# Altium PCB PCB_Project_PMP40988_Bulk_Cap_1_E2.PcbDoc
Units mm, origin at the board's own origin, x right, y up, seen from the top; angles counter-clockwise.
Board outline 29.99 x 33.8 mm, 2 copper layers (Top Layer, Bottom Layer), stack 1.646 mm thick; 1 components, 2 nets, 2 pads, 50 vias.
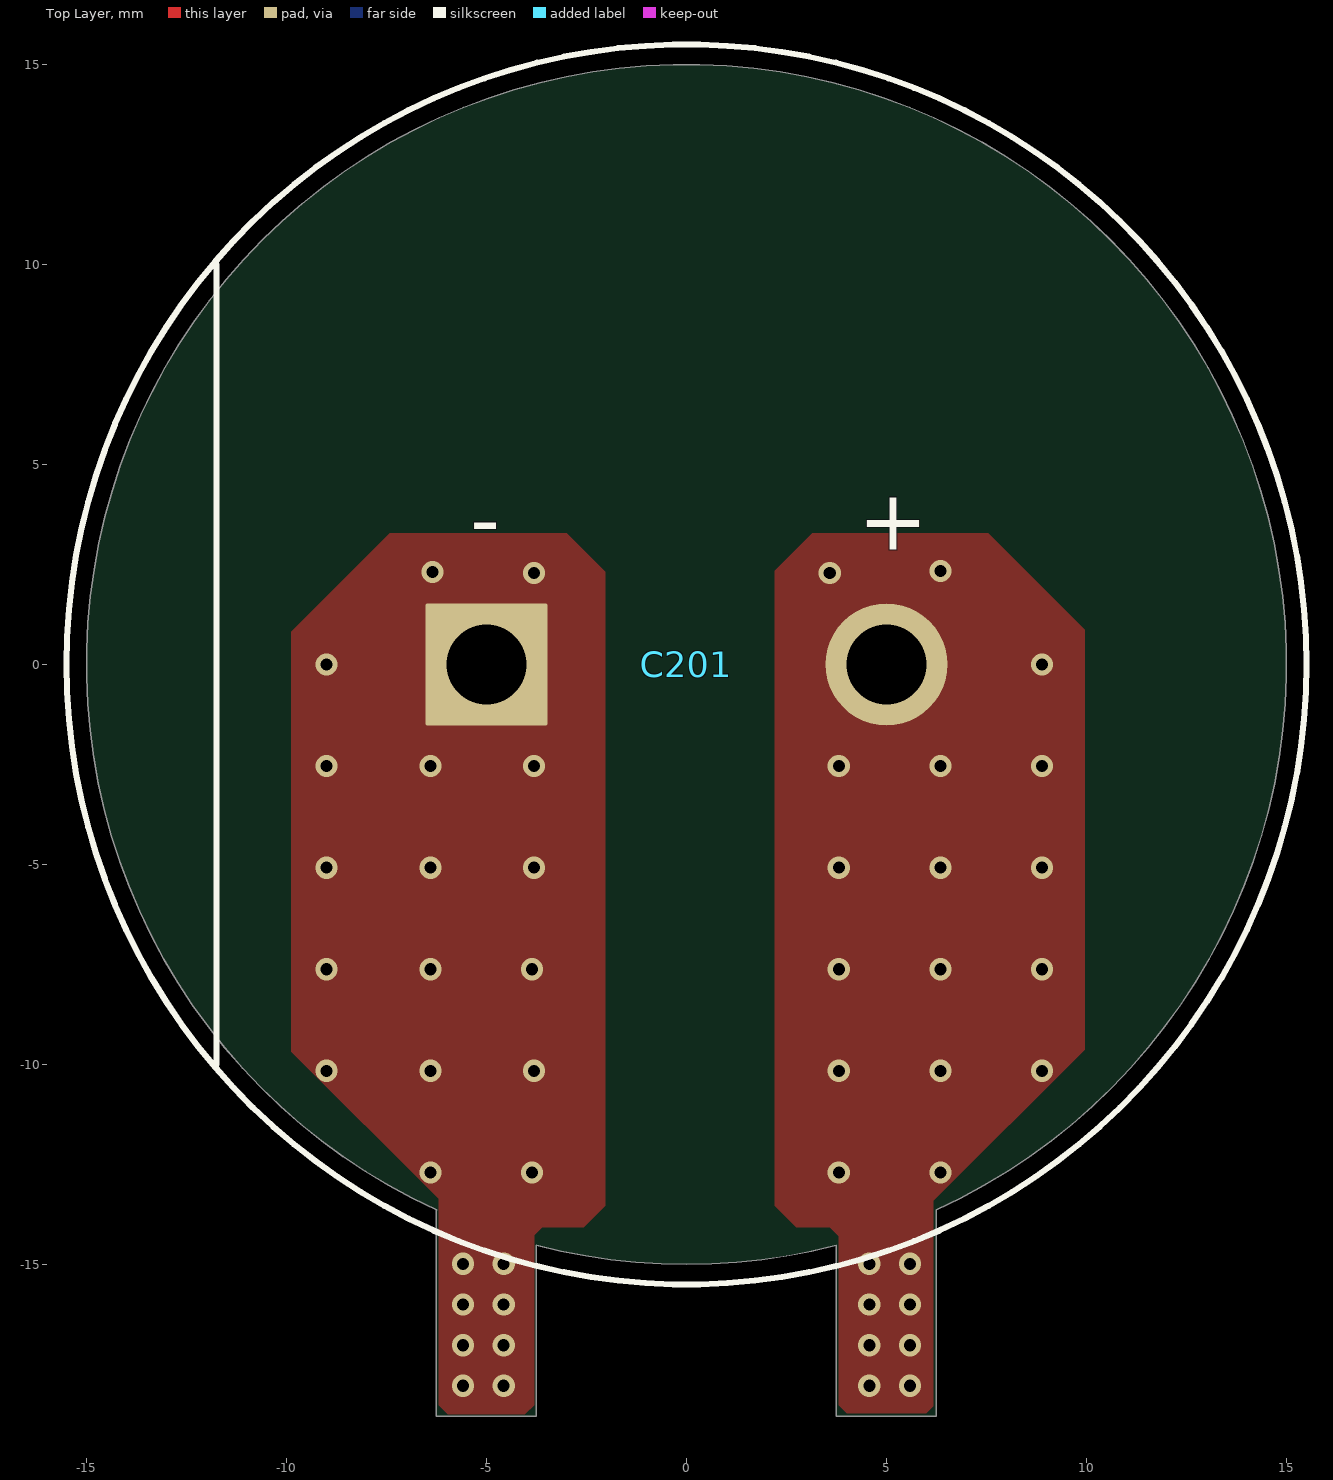
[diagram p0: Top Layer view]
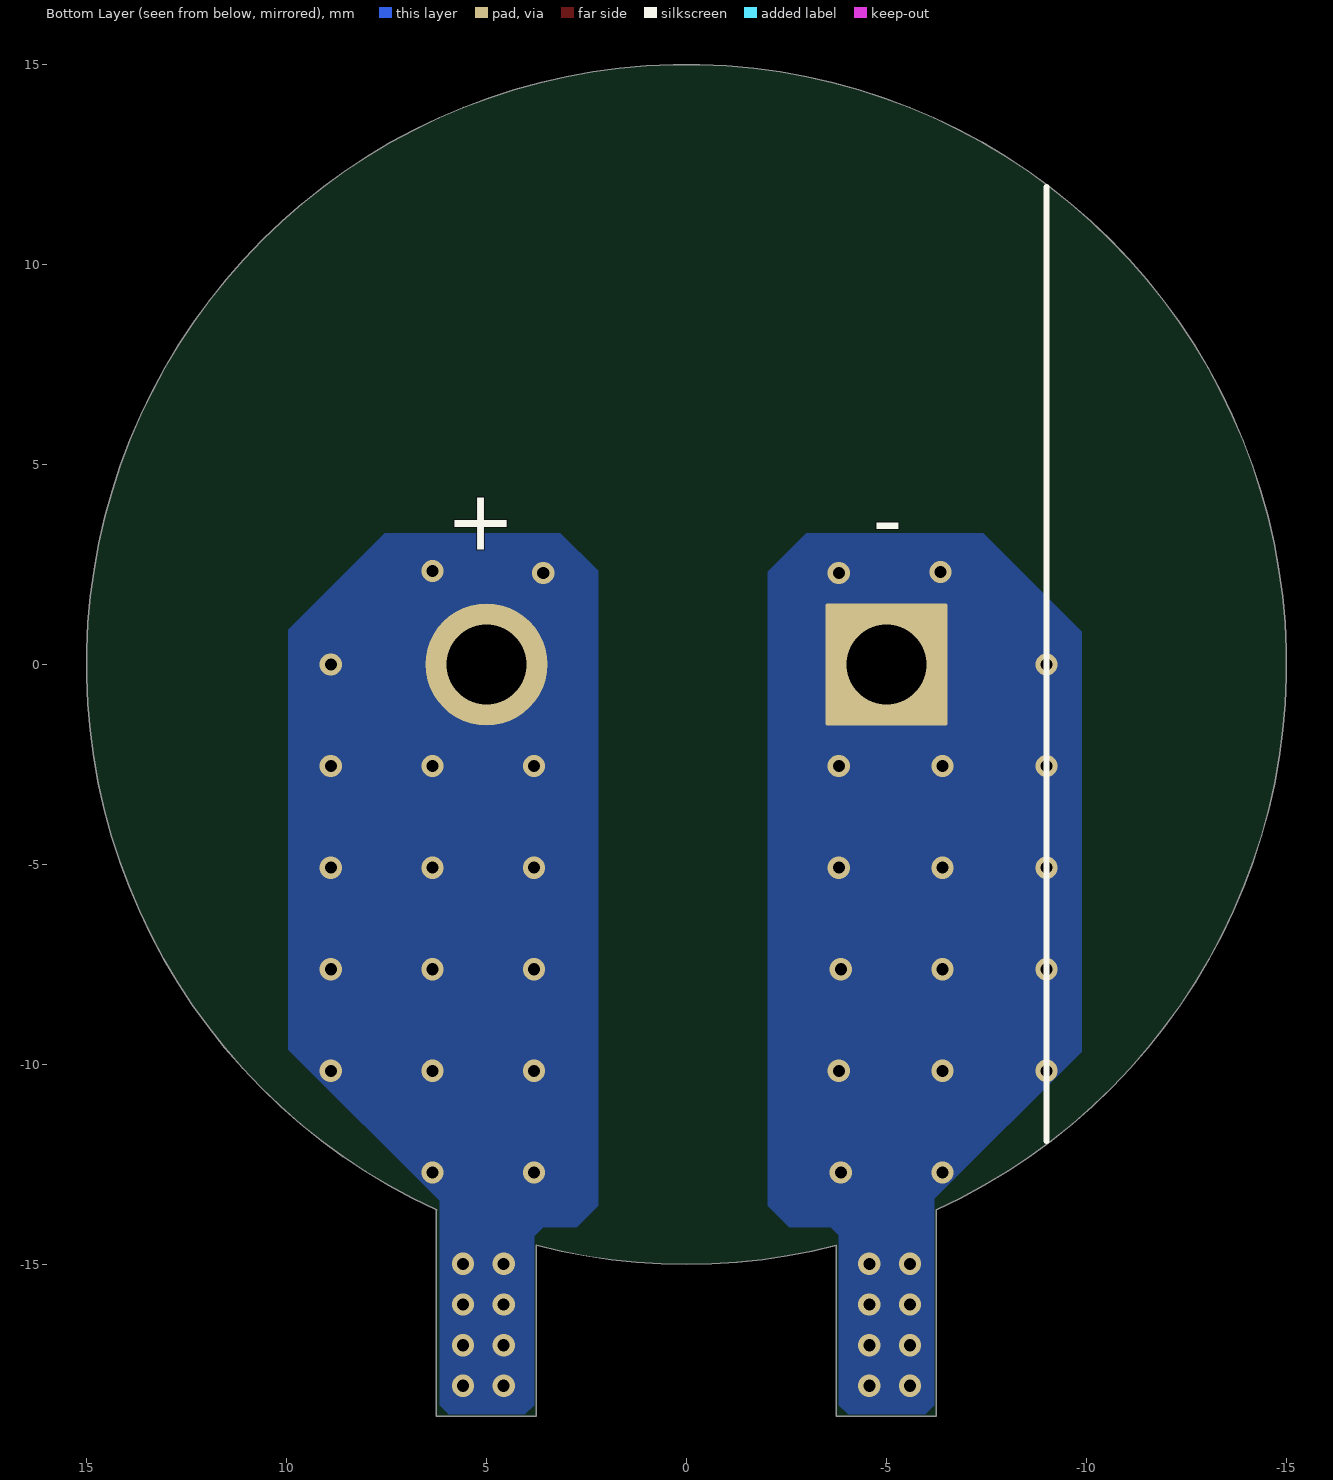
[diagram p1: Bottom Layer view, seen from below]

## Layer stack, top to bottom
Top Solder: solder mask 0.0102, Solder Resist, Dk 3.5
Top Layer: signal copper 0.0711
Dielectric1: core 1.5037, FR-4 High Tg, Dk 4.8
Bottom Layer: signal copper 0.0711
Bottom Solder: solder mask 0.0102, Solder Resist, Dk 3.5

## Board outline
-6.25,-18.8 -3.75,-18.8 -3.75,-14.526 -3.75,-14.524 ccw(c0,0) 3.743,-14.526 3.75,-14.526 3.75,-18.8 6.25,-18.8 6.25,-13.642 6.248,-13.637 ccw(c0,0) -6.248,-13.637 -6.25,-13.642

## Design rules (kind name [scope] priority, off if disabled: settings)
AcuteAngle [All] p1: minimum=4.50000000000000E+0001 checktracksonly=FALSE
AssemblyTestPointUsage [All] p1: valid=2
Clearance Clearance_3 [InNet('EARTH') vs Not InNet('EARTH') And Not InNet('12VS')] p1: gap=5.08 ignorepadtopadclearanceinfootprint=FALSE except(0: Arc-Hole Track-Hole SMDPad-Hole THPad-Hole Via-Hole Fill-Hole Poly-Hole Region-Hole Text-Hole)
Clearance Clearance_1 [InNetClass('HV') vs InNetClass('MV')] p2: gap=0.635 ignorepadtopadclearanceinfootprint=FALSE except(0: Arc-Hole Track-Hole SMDPad-Hole THPad-Hole Via-Hole Fill-Hole Poly-Hole Region-Hole Text-Hole)
Clearance Clearance_2 [InNetClass('HV') vs Not InNetClass('HV')] p3: gap=1.27 ignorepadtopadclearanceinfootprint=FALSE except(0: Arc-Hole Track-Hole SMDPad-Hole THPad-Hole Via-Hole Fill-Hole Poly-Hole Region-Hole Text-Hole)
Clearance Clearance_Keepouts [((IsTrack Or IsArc) And Not InPoly) And IsFree and IsKeepOut vs ((IsTrack Or IsArc) And Not InPoly) And IsFree and IsKeepOut] p4: gap=0 ignorepadtopadclearanceinfootprint=FALSE
Clearance Clearance_BoardEdge_MountingHoles [OnCopper and InComponentClass('Mounting Holes') vs IsKeepOut] p5: gap=1.016 ignorepadtopadclearanceinfootprint=FALSE except(0: Arc-Hole Track-Hole SMDPad-Hole THPad-Hole Via-Hole Fill-Hole Poly-Hole Region-Hole Text-Hole)
Clearance Clearance_BoardEdge_Poly [OnCopper and InPoly vs IsKeepOut] p6: gap=0.635 ignorepadtopadclearanceinfootprint=FALSE except(0: Arc-Hole Track-Hole SMDPad-Hole THPad-Hole Via-Hole Fill-Hole Poly-Hole Region-Hole Text-Hole)
Clearance Clearance_BoardEdge [OnCopper and Not InComponentClass('Logo') and not InComponentClass('FiducialMark') and not InRegion(1000,500,4000,800) and Not IsKeepout vs IsKeepOut] p7: gap=1.905 ignorepadtopadclearanceinfootprint=FALSE except(0: Arc-Hole Track-Hole SMDPad-Hole THPad-Hole Via-Hole Fill-Hole Poly-Hole Region-Hole Text-Hole)
Clearance Clearance_Poly [InPolygon] p8: gap=0.254 ignorepadtopadclearanceinfootprint=FALSE except(0: Arc-Hole Track-Hole SMDPad-Hole THPad-Hole Via-Hole Fill-Hole Poly-Hole Region-Hole Text-Hole)
Clearance [All] p9: gap=0.2 ignorepadtopadclearanceinfootprint=FALSE except(0: Arc-Hole Track-Hole SMDPad-Hole THPad-Hole Via-Hole Fill-Hole Poly-Hole Region-Hole Text-Hole)
ComponentClearance ComponentClearance_MountingHoles_FiducialMarks [InComponentClass('Mounting Holes') vs InComponentClass('FiducialMark')] p1: gap=0.508 collisioncheckmode=3 verticalgap=0.254 showdistances=FALSE
ComponentClearance ComponentClearance_Shunt [InComponentClass('Header') vs InComponentClass('Shunt')] p2: gap=0 collisioncheckmode=3 verticalgap=0 showdistances=FALSE
ComponentClearance ComponentClearance_Logo [InComponentClass('Logo')] p3: gap=0.127 collisioncheckmode=3 verticalgap=0.254 showdistances=FALSE
ComponentClearance ComponentClearance_ScrewToNut [(HasFootprint('NY PMS 440 0025 PH')) vs (HasFootprint('Keystone_1902C'))] p4: gap=0.508 collisioncheckmode=3 verticalgap=2540 showdistances=FALSE
ComponentClearance ComponentClearance_MountingHoles [InComponentClass('Mounting Holes')] p5: gap=0.508 collisioncheckmode=3 verticalgap=0.254 showdistances=FALSE
ComponentClearance ComponentClearance_SmallPassives [HasFootprint('0201*') or HasFootprint('0402*') or HasFootprint('0508') or HasFootprint('0603*') or HasFootprint('0612') or HasFootprint('0805*') or HasFootprint('0815*') or HasFootprint('0830*') or HasFootprint('1206*') or HasFootprint('1210*') or HasFootprint('1808*') or HasFootprint('1812*') or HasFootprint('1825*') or HasFootprint('2010*') or HasFootprint('2220*') or HasFootprint('2225*') or HasFootprint('2512*') or HasFootprint('2728*') or HasFootprint('3518*') vs HasFootprint('0201*') or HasFootprint('0402*') or HasFootprint('0508') or HasFootprint('0603*') or HasFootprint('0612') or HasFootprint('0805*') or HasFootprint('0815*') or HasFootprint('0830*') or HasFootprint('1206*') or HasFootprint('1210*') or HasFootprint('1808*') or HasFootprint('1812*') or HasFootprint('1825*') or HasFootprint('2010*') or HasFootprint('2220*') or HasFootprint('2225*') or HasFootprint('2512*') or HasFootprint('2728*') or HasFootprint('3518*')] p6: gap=0.508 collisioncheckmode=3 verticalgap=0.508 showdistances=FALSE
ComponentClearance ComponentClearance_THtoSMT [IsThruComponent vs IsSMTComponent] p7: gap=0.254 collisioncheckmode=3 verticalgap=0.254 showdistances=FALSE
ComponentClearance ComponentClearance_THtoTH [IsThruComponent vs IsThruComponent] p8: gap=0.254 collisioncheckmode=3 verticalgap=0.254 showdistances=FALSE
ComponentClearance [All] p9: gap=0.254 collisioncheckmode=3 verticalgap=0.254 showdistances=FALSE
DiffPairsRouting [All] p1: maxlimit=2.54 minlimit=0.254 mostfreqgap=0.254 toplayer_minwidth=0.381 toplayer_maxwidth=0.381 toplayer_prefwidth=0.381 bottomlayer_minwidth=0.381 bottomlayer_maxwidth=0.381 bottomlayer_prefwidth=0.381 maxuncoupledlength=25.4
FabricationTestPointUsage TestPointUsage [All] p1: valid=2 allowmultiple=FALSE
FabricationTestpoint Testpoint [All] p1: side=3 testpointundercomponent=TRUE minsize=1.016 maxsize=2.54 preferedsize=1.524 minholesize=0 maxholesize=1.016 preferedholesize=0.813 testpointgrid=0.025 allowsidetop=TRUE allowsidebottom=TRUE usegrid=TRUE gridtolerance=0
FanoutControl Fanout_LCC [IsLCC] p1: bgadir=Out bgaviamode=Centered fanoutstyle=Auto fanoutdirection=Alternating viagrid=0.025 // Fanout_LCC (Default Rule)
FanoutControl Fanout_BGA [IsBGA] p2: bgadir=Out bgaviamode=Centered fanoutstyle=Auto fanoutdirection=Alternating viagrid=0.025 // Fanout_BGA (Default Rule)
FanoutControl Fanout_Default [All] p4: bgadir=Out bgaviamode=Centered fanoutstyle=Auto fanoutdirection=Alternating viagrid=0.025 // Fanout_Default (Default Rule)
FanoutControl Fanout_Small [(CompPinCount < 5)] p5: bgadir=Out bgaviamode=Centered fanoutstyle=Auto fanoutdirection=OutThenIn viagrid=0.025 // Fanout_Small (Default Rule)
Height [All] p1: minheight=0 maxheight=76.2 prefheight=12.7
HoleSize [All] p1: absolutevalues=TRUE maxlimit=6.375 minlimit=0.178 maxpercent=80.000 minpercent=20.000
MinimumAnnularRing MinimumAnnularRing_ThermalPadVias [IsVia and InAnyComponent] p1: minimumring=0.15
MinimumAnnularRing [All] p2: minimumring=0.124
MinimumSolderMaskSliver MinimumSolderMaskSliver_Logo [InComponentClass('Logo') vs InComponentClass('Logo')] p1: minsoldermaskwidth=0.018
MinimumSolderMaskSliver [All] p2: minsoldermaskwidth=0.051
PlaneConnect [All] p1: planeconnectstyle=Direct reliefexpansion=0.254 reliefentries=4 reliefconductorwidth=0.254 reliefairgap=0.254
PolygonConnect [All] p1: connectstyle=Direct reliefconductorwidth=0.254 reliefentries=4 polygonreliefangle="90 Angle" airgapwidth=0.254
RoutingVias ThermalPadVias [IsVia and InAnyComponent] p1: holewidth=0.2 width=0.5 viastyle="Through Hole" minholewidth=0.2 minwidth=0.5 maxholewidth=0.33 maxwidth=0.6
RoutingVias [All] p2: holewidth=0.406 width=0.864 viastyle="Through Hole" minholewidth=0.2 minwidth=0.508 maxholewidth=1.016 maxwidth=1.651
SilkToBoardRegionClearance [Not ((IsComment or IsDesignator) And (Hide <> 'False')) and not InRegion(1000,500,4000,800)] p1:
SilkToSilkClearance SilkToSilkClearance_Pb-FreeLogo [(HasFootprint('Pb-Free_Overlay_Medium') OR HasFootprint('Pb-Free_Overlay_Small')) vs (HasFootprint('Pb-Free_Overlay_Medium') OR HasFootprint('Pb-Free_Overlay_Small'))] p1: silktosilkclearance=0
SilkToSilkClearance [All] p2: silktosilkclearance=0.025
SilkToSolderMaskClearance "Silk to Solder Mask Opening" [All] p1: minsilkscreentomaskgap=0.025 clearancetoexposedcopper=FALSE
SolderMaskExpansion [All] p1: expansion=0.05 istentingtop=FALSE
Width [All] p1: maxlimit=2.54 minlimit=0.152 preferedwidth=0.254 checkconnectedcopper=TRUE
14 further rules are at their usual default settings.

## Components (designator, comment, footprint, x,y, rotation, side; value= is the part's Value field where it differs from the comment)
C201 "450MXK820MEFCFA30X60" FP-450MXK820MEFCFA30X60_RADIAL-MFG 0,0 r0 top value=820µF

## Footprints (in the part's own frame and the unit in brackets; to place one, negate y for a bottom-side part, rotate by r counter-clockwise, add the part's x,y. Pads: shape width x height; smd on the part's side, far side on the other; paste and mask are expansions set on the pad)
FP-450MXK820MEFCFA30X60_RADIAL-MFG [mm]
  rrect3% 3.05x3.05 hole 2 paste-1000 mask+0: 1(-5,0)
  round 3.05 hole 2 paste-1000 mask+0: 2(5,0)
  silkscreen extent -15.5,-15.5 15.5,15.5, body extent -15.6,-15.6 15.6,15.6, height 0.25

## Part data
C201: library part CMP-0097399-1, "Cap Aluminum 820uF 450V 20% Snap-In Aluminum Cylindrical Can 2.77A 3000 hr 105°C Ammo Pack", Digikey Part Number=450MXK820MEFCFA30X60-ND, Leakage Current=1822.36uA, Manufacturer=Rubycon, Operating Temperature Range="-25°C to +105°C", Tolerance_%=20%, ValueDisplayed=820uF

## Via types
v1: diameter 0.559, hole 0.305, Top Layer to Bottom Layer, tented both sides, 50 vias

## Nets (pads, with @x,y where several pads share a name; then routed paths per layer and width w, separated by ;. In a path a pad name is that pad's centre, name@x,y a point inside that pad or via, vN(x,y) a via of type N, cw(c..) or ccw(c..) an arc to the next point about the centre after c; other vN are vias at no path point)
Vbulk: C201.2
  other v1: 4.572,-18.034 5.588,-18.034 4.572,-17.018 5.588,-17.018 4.572,-16.002 5.588,-16.002 4.572,-14.986 5.588,-14.986 3.81,-12.7 6.35,-12.7 3.81,-10.16 6.35,-10.16 8.89,-10.16 3.81,-7.62 6.35,-7.62 8.89,-7.62 3.81,-5.08 6.35,-5.08 8.89,-5.08 3.81,-2.54 6.35,-2.54 8.89,-2.54 8.89,0 3.581,2.286 6.35,2.337
Vbulk-: C201.1
  other v1: -5.588,-18.034 -4.572,-18.034 -5.588,-17.018 -4.572,-17.018 -5.588,-16.002 -4.572,-16.002 -5.588,-14.986 -4.572,-14.986 -6.401,-12.7 -3.861,-12.7 -9,-10.16 -6.401,-10.16 -3.81,-10.16 -9,-7.62 -6.401,-7.62 -3.861,-7.62 -9,-5.08 -6.401,-5.08 -3.81,-5.08 -9,-2.54 -6.401,-2.54 -3.81,-2.54 -9,0 -3.81,2.286 -6.35,2.311

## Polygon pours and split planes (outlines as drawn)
Vbulk on Top Layer "Top Layer-No Net 1" (solid, remove dead copper, pour order 4): 2.21,2.337 3.15,3.277 7.544,3.277 9.957,0.864 9.957,-9.627 6.172,-13.411 6.172,-18.542 5.994,-18.72 4.013,-18.72 3.81,-18.517 3.81,-14.3 3.581,-14.072 2.743,-14.072 2.21,-13.538
Vbulk- on Top Layer "Top Layer-No Net" (solid, remove dead copper, pour order 2): -7.417,3.277 -9.881,0.813 -9.881,-9.677 -6.198,-13.36 -6.198,-18.517 -5.969,-18.745 -4.039,-18.745 -3.81,-18.517 -3.81,-14.275 -3.607,-14.072 -2.565,-14.072 -2.032,-13.538 -2.032,2.311 -2.997,3.277
Vbulk on Bottom Layer "Top Layer-No Net 1" (solid, remove dead copper, pour order 8): 2.21,2.337 3.15,3.277 7.544,3.277 9.957,0.864 9.957,-9.627 6.172,-13.411 6.172,-18.517 5.944,-18.745 4.039,-18.745 3.81,-18.517 3.81,-14.3 3.581,-14.072 2.743,-14.072 2.21,-13.538
Vbulk- on Bottom Layer "Top Layer-No Net" (solid, remove dead copper, pour order 6): -7.417,3.277 -9.881,0.813 -9.881,-9.677 -6.198,-13.36 -6.198,-18.517 -5.969,-18.745 -4.039,-18.745 -3.81,-18.517 -3.81,-14.275 -3.607,-14.072 -2.565,-14.072 -2.032,-13.538 -2.032,2.311 -2.997,3.277

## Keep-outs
Keep-Out Layer:
  text ".Layer_Name" at -31.775,-57.594 h1.52

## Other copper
Top Layer:
  text ".Layer_Name" at -31.775,-57.594 h1.52
Bottom Layer:
  text ".Layer_Name" at -31.775,-57.594 h1.52

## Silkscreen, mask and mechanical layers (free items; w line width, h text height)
Top Overlay:
  text "-" at -5.41,2.896 h1.52
  text "+" at 4.293,2.87 h1.52
  text ".Layer_Name" at -31.775,-57.594 h1.52
Bottom Overlay:
  lines w0.152: -9,-11.913 -9,11.938
  text "-" at -5.41,2.896 h1.52
  text "+" at 4.267,2.87 h1.52
  text ".Layer_Name" at -31.775,-57.594 h1.52
Top Paste:
  text ".Layer_Name" at -31.775,-57.594 h1.52
Bottom Paste:
  text ".Layer_Name" at -31.775,-57.594 h1.52
Top Solder:
  rectangle: 3.785,-18.72 6.198,-14.478
  rectangle: -6.198,-18.745 -3.785,-14.478
  text ".Layer_Name" at -31.775,-57.594 h1.52
  text ".Layer_Name" at -31.775,-57.594 h1.52
Bottom Solder:
  rectangle: 3.785,-18.745 6.198,-14.478
  rectangle: -6.198,-18.745 -3.785,-14.478
  text ".Layer_Name" at -31.775,-57.594 h1.52
Drill Guide:
  text ".Layer_Name" at -31.775,-57.594 h1.52
M1 Board Outline:
  lines w0.254: -6.25,-13.642 -6.25,-18.8 -3.75,-18.8 -3.75,-14.526 ; -6.248,-13.637 cw(c0,0) 6.248,-13.637 ; -3.75,-14.524 ccw(c0,0) 3.743,-14.526 ; 3.75,-14.526 3.75,-18.8 6.25,-18.8 6.25,-13.642
  text ".Layer_Name" at -31.775,-57.594 h1.52
M2 Board Dimensions:
  rectangle: -43.256,-45.949 -33.731,-42.774
  rectangle: -46.431,-42.774 -43.256,-39.599
  lines w0.178: -46.431,-42.774 -21.031,-42.774 ; -43.256,-45.949 -43.256,-39.599 ; -40.081,-45.949 -40.081,-39.599 ; -33.731,-45.949 -33.731,-39.599 ; -27.381,-45.949 -27.381,-39.599 ; -46.431,-45.949 -46.431,-39.599 -21.031,-39.599 -21.031,-45.949 -46.431,-45.949
  text ".Layer_Name" at -31.775,-57.594 h1.52
M3 3D STEP Top:
  text ".Layer_Name" at -31.775,-57.594 h1.52
M4 3D STEP Bottom:
  text ".Layer_Name" at -31.775,-57.594 h1.52
M5 Assembly Top:
  lines w0.254: -53.848,-59.415 113.792,-59.415 ; -53.848,-54.25 113.843,-54.25 ; -53.848,-49.085 -53.848,-64.579 47.879,-64.579 113.843,-64.579 113.843,-49.086 -53.835,-49.086 -53.835,-64.579 -13.818,-64.579 ; 8.763,-64.579 8.763,-49.086 ; 40.945,-54.25 40.945,-49.086 ; 62.281,-54.25 62.281,-49.086 ; 78.08,-64.745 78.08,-59.593
  text "COMPONENTS MARKED 'DNP' SHOULD NOT BE POPULATED." at -17.132,-43.878 h1.52
  text "ASSEMBLY VARIANT:" at -17.145,-46.812 h1.52
  text ".VariantName" at 9.169,-46.812 h1.52
  text "PCB VIEWED FROM TOP SIDE" at -52.235,-52.443 h1.52
  text "BOARD #:" at 10.668,-52.443 h1.52
  text ".PRJ_Number" at 24.524,-52.443 h1.52
  text "REV:" at 45.974,-52.443 h1.52
  text ".PCB_Rev" at 53.378,-52.443 h1.52
  text "SVN REV:" at 67.259,-52.443 h1.52
  text ".VersionControl_RevNumber" at 80.112,-52.443 h1.52
  text "TID #:" at 10.668,-57.607 h1.52
  text ".TID" at 24.524,-57.607 h1.52
  text "PLOT NAME =" at -52.235,-62.823 h1.52
  text ".plot_File_Name" at -31.775,-62.823 h1.52
  text "GENERATED    :" at 10.719,-62.823 h1.52
  text ".Print_Date" at 32.804,-62.823 h1.52
  text ".Print_Time" at 51.321,-62.823 h1.52
  text "TEXAS INSTRUMENTS" at 83.439,-62.823 h1.52
M6 Assembly Bottom:
  lines w0.254: -53.861,-54.263 113.83,-54.263 ; -53.81,-59.428 113.83,-59.428 ; -18.098,-64.757 -18.098,-59.605 ; -2.299,-54.263 -2.299,-49.098 ; 19.037,-54.263 19.037,-49.098 ; 51.219,-64.592 51.219,-49.098 ; 73.8,-64.592 113.817,-64.592 113.817,-49.098 -53.861,-49.098 -53.861,-64.592 12.103,-64.592 113.83,-64.592 113.83,-49.098
  text "COMPONENTS MARKED 'DNP' SHOULD NOT BE POPULATED." at 108.56,-43.866 h1.52
  text ".VariantName" at 82.042,-46.812 h1.52
  text "ASSEMBLY VARIANT:" at 108.433,-46.812 h1.52
  text ".VersionControl_RevNumber" at -20.13,-52.455 h1.52
  text "SVN REV:" at -7.277,-52.455 h1.52
  text ".PCB_Rev" at 6.604,-52.455 h1.52
  text "REV:" at 14.008,-52.455 h1.52
  text ".PRJ_Number" at 35.458,-52.455 h1.52
  text "BOARD #:" at 49.314,-52.455 h1.52
  text "PCB VIEWED FROM BOTTOM SIDE" at 112.217,-52.455 h1.52
  text ".TID" at 35.458,-57.62 h1.52
  text "TID #:" at 49.314,-57.62 h1.52
  text "TEXAS INSTRUMENTS" at -23.457,-62.835 h1.52
  text ".Print_Time" at 8.661,-62.835 h1.52
  text ".Print_Date" at 27.178,-62.835 h1.52
  text "GENERATED    :" at 49.263,-62.835 h1.52
  text ".plot_File_Name" at 91.757,-62.835 h1.52
  text "PLOT NAME =" at 112.217,-62.835 h1.52
M9 Title Sheet:
  drawing of 57 lines, arcs and shapes, not listed
  text "1" at -27.639,168.338 h1.78
  text "2" at 35.75,168.338 h1.78
  text "3" at 98.98,168.338 h1.78
  text "4" at 162.649,168.338 h1.78
  text "5" at 226.123,168.338 h1.78
  text "6" at 289.75,168.338 h1.78
  text "A" at -57.01,139.306 h1.78
  text "A" at 318.91,139.306 h1.78
  text "B" at -57.01,78.854 h1.78
  text "B" at 318.91,78.854 h1.78
  text "C" at -57.01,18.529 h1.78
  text "C" at 318.91,18.529 h1.78
  text "PROJECT TITLE:" at 241.694,-28.74 h1.14
  text ".PRJ_Title" at 242.964,-32.127 h1.78
  text "DESIGNED FOR:" at 241.694,-36.386 h1.14
  text ".PRJ_Customer" at 242.964,-39.941 h1.78
  text "D" at -57.01,-41.669 h1.78
  text "D" at 318.91,-41.669 h1.78
  text "FILE NAME:" at 241.694,-44.005 h1.14
  text ".PCB_File_Name_No_Path" at 242.964,-47.053 h1.78
  text "Texas Instruments (TI) and/or its licensors do not warrant the accuracy or completeness of this specification" at 115.468,-51.164 h1.14
  text "ENGINEER:" at 241.694,-51.371 h1.14
  text "LAYOUT BY:" at 279.921,-51.371 h1.14
  text "or any information contained therein. TI and/or its licensors do not warrant that this design will meet" at 114.326,-54.026 h1.14
  text ".PRJ_Engineer" at 242.964,-55.308 h1.78
  text ".PCB_Layout" at 281.203,-55.308 h1.78
  text "the specifications, will be suitable for your application or fit for any particular purpose, or will operate in" at 114.326,-56.888 h1.14
  text ".Layer_Name" at -31.775,-57.594 h1.52
  text "ALTIUM DESIGNER VERSION:" at 279.921,-59.245 h1.14
  text "an implementation. TI and/or its licensors do not warrant that the design is production worthy. You should" at 114.326,-59.749 h1.14
  text "completely validate and test your design implementation to confirm the system functionality for your application." at 115.468,-62.611 h1.14
  text ".print_Scale" at 242.964,-62.632 h1.78
  text ".Application_BuildNumber" at 281.203,-62.632 h1.78
  text "1" at -27.639,-67.882 h1.78
  text "2" at 35.75,-67.882 h1.78
  text "3" at 98.98,-67.882 h1.78
  text "4" at 162.649,-67.882 h1.78
  text "5" at 226.123,-67.882 h1.78
  text "6" at 289.75,-67.882 h1.78
M10 Fab Notes:
  drawing of 189 lines, arcs and shapes, not listed
  text "DESIGN INFORMATION" at 268.072,125.658 h1.52
  text "MIN. TRACK WIDTH:" at 251.7,122.302 h1.52
  text "8" at 279.545,122.302 h1.52
  text "MIL" at 283.476,122.302 h1.52
  text "7.874" at 275.319,119.211 h1.52
  text "MIN. CLEARANCE:" at 251.7,119.149 h1.52
  text "MIL" at 283.476,119.149 h1.52
  text "MIN. VIA PAD SIZE:" at 251.7,115.997 h1.52
  text "24" at 278.783,115.997 h1.52
  text "MIL" at 283.476,115.997 h1.52
  text "0.05mm (2MIL)" at 269.353,112.697 h1.52
  text "MINIMUM ANNULAR RING" at 243.338,112.488 h1.52
  text "EXTERNAL" at 287.336,112.488 h1.52
  text "PER" at 248.418,109.691 h1.52
  text "IPC-D-275 CLASS 2 LEVEL C" at 254.006,109.691 h1.52
  text "MIL, HOLES" at 291.807,107.139 h1.52
  text "+/-" at 281.838,106.921 h1.52
  text "+/-" at 303.53,106.921 h1.52
  text "REGISTRATION TOLERANCES:" at 243.338,106.894 h1.52
  text "METAL" at 273.812,106.894 h1.52
  text "5" at 288.448,106.894 h1.52
  text "3" at 309.606,106.894 h1.52
  text "MIL" at 312.559,106.894 h1.52
  text "HOLE SIZE TOLERANCE (UNLESS OTHERWISE SPECIFIED):" at 243.338,104.397 h1.52
  text "+/-" at 303.53,104.324 h1.52
  text "3" at 309.606,104.297 h1.52
  text "MIL" at 312.559,104.297 h1.52
  text "MATERIAL:" at 241.439,100.8 h1.52
  text "FR-4 High Tg" at 266.494,97.536 h1.52
  text "X" at 262.826,97.333 h1.52
  text "FR-408" at 252.132,97.218 h1.52
  text "OTHER" at 289.927,97.218 h1.52
  text "62 MIL (1.6mm) +/-10%" at 260.263,93.585 h1.52
  text "X" at 257.212,93.523 h1.52
  text "THICKNESS:" at 243.338,93.376 h1.52
  text "OTHER" at 292.899,93.376 h1.52
  text "TOLERANCE:" at 243.338,89.863 h1.52
  text "X" at 264.883,89.863 h1.52
  text "ANSI IPC-6012 TYPE 3 CLASS 2" at 269.404,89.863 h1.52
  text "OTHER +/-" at 269.404,86.201 h1.52
  text "BOW & TWIST:" at 243.338,82.513 h1.52
  text "X" at 264.883,82.513 h1.52
  text "ANSI IPC-6012 TYPE 3 CLASS 2" at 269.404,82.513 h1.52
  text "OTHER +/-" at 269.404,78.787 h1.52
  text "DRILLING:" at 241.439,75.469 h1.52
  text "NC_DRILL FILES" at 286.168,72.797 h1.52
  text "REFERENCE:" at 243.338,72.697 h1.52
  text "X" at 260.032,72.695 h1.52
  text "AS SHOWN" at 264.553,72.697 h1.52
  text "X" at 282.917,72.697 h1.52
  text "OTHER" at 293.737,69.084 h1.52
  text "PTH COPPER THICKNESS:" at 243.33,68.995 h1.52
  text "X" at 272.266,68.995 h1.52
  text "20-30 um" at 275.517,68.995 h1.52
  text "BOARD FINISH:" at 241.439,65.246 h1.52
  text "SILKSCREEN:" at 245.381,62.448 h1.52
  text "X" at 269.709,62.448 h1.52
  text "TOP" at 272.681,62.448 h1.52
  text "X" at 282.663,62.448 h1.52
  text "BOTTOM" at 285.66,62.448 h1.52
  text "SILKSCREEN COLOR:" at 245.381,58.507 h1.52
  text "X" at 269.684,58.507 h1.52
  text "WHITE" at 272.681,58.507 h1.52
  text "OTHER" at 285.66,58.507 h1.52
  text "X" at 273.011,54.863 h1.52
  text "GREEN" at 276.008,54.863 h1.52
  text "OTHER" at 291.705,54.863 h1.52
  text "SOLDER RESIST COLOR:" at 245.381,54.689 h1.52
  text "X" at 273.011,50.945 h1.52
  text "MATTE" at 276.008,50.945 h1.52
  text "SEMI-GLOSS" at 291.694,50.929 h1.52
  text "IMMERSION GOLD (ENIG)" at 268.388,46.557 h1.52
  text "ENEPIG" at 302.362,46.373 h1.52
  text "SURFACE FINISH:" at 241.439,46.348 h1.52
  text "X" at 263.867,46.348 h1.52
  text "IMM. TIN/SILVER OR EQUIV" at 249.809,42.86 h1.52
  text "OTHER" at 286.168,42.76 h1.52
  text "ARRAY/PANEL:" at 241.439,38.813 h1.52
  text "CUT AND TRIM PER M1 BOARD OUTLINE" at 268.388,38.605 h1.52
  text "N.C. ROUTE" at 268.388,35.151 h1.52
  text "X" at 285.863,35.151 h1.52
  text "V. SCORE" at 290.384,35.151 h1.52
  text "CERTIFICATION:" at 241.439,31.871 h1.52
  text "MATERIALS AND WORKMANSHIP FOR ALL PCBS" at 259.854,31.871 h1.52
  text "TO MEET OR EXCEED THE REQUIREMENTS OF:" at 259.854,29.482 h1.52
  text "X" at 250.646,26.215 h1.52
  text "ANSI IPC-A-600F CLASS ->" at 253.897,26.215 h1.52
  text "X" at 295.757,26.215 h1.52
  text "2" at 298.551,26.215 h1.52
  text "1" at 290.55,26.177 h1.52
  text "3" at 307.542,26.177 h1.52
  text "X" at 271.271,22.464 h1.52
  text "RoHS" at 274.522,22.464 h1.52
  text "OTHER" at 290.89,22.464 h1.52
  text "PER ORDER" at 300.975,22.464 h1.52
  text "ALL BOARDS MUST MEET OR EXCEED UL94-V0 REQUIREMENTS." at 242.138,18.556 h1.52
  text "PCB MUST BEAR THE UL94V-0 UL REGISTERED MATERIAL ID NUMBER" at 242.138,15.608 h1.52
  text "ADDITIONAL REQUIREMENTS:" at 241.439,11.305 h1.52
  text "MICROSECTION:" at 243.338,8.584 h1.52
  text "YES" at 266.343,8.584 h1.52
  text "REQUIRED" at 288.225,4.918 h1.52
  text "BARE BOARD ELEC. TEST:" at 243.338,4.845 h1.52
  text "NONE" at 276.503,4.845 h1.52
  text "X" at 285.228,4.845 h1.52
  text "PER ORDER" at 303.262,4.845 h1.52
  text "XX MIL VIAS REQUIRE NON-CONDUCTIVE FILL AND PLANARIZE" at 247.609,-0.36 h1.5
  text "XX MIL VIAS REQUIRE CONDUCTIVE FILL AND PLANARIZE" at 247.812,-3.001 h1.52
  text "OUTER XX MIL TRACES REQUIRE 50 OHM SINGLE-ENDED IMPEDANCE" at 247.787,-7.151 h1.47
  text "LAYER 2 & 3 (INNER LAYERS) XX MIL WIDE, XX MIL SPACE / TRACES REQUIRE 100 OHM DIFFERENTIAL IMPEDANCE" at 247.584,-13.138 h1.52
  text ".Layer_Name" at -31.775,-57.594 h1.52
M11 Gerber Information:
  lines w0.254: -53.848,-59.415 113.792,-59.415 ; -53.848,-54.25 113.843,-54.25 ; -53.848,-49.085 -53.848,-64.579 47.879,-64.579 113.843,-64.579 113.843,-49.086 -53.835,-49.086 -53.835,-64.579 -13.818,-64.579 ; 8.763,-64.579 8.763,-49.086 ; 40.945,-54.25 40.945,-49.086 ; 62.281,-54.25 62.281,-49.086 ; 78.08,-64.745 78.08,-59.593
  text "ALL ARTWORK VIEWED FROM TOP SIDE" at -52.235,-52.443 h1.52
  text "BOARD #:" at 10.668,-52.443 h1.52
  text ".PRJ_Number" at 24.524,-52.443 h1.52
  text "REV:" at 45.974,-52.443 h1.52
  text ".PCB_Rev" at 53.378,-52.443 h1.52
  text "SVN REV:" at 67.259,-52.443 h1.52
  text ".VersionControl_RevNumber" at 80.112,-52.443 h1.52
  text "LAYER NAME =" at -52.235,-57.594 h1.52
  text "TID #:" at 10.668,-57.607 h1.52
  text ".TID" at 24.524,-57.607 h1.52
  text "PLOT NAME =" at -52.235,-62.823 h1.52
  text ".plot_File_Name" at -31.775,-62.823 h1.52
  text "GENERATED    :" at 10.719,-62.823 h1.52
  text ".Print_Date" at 32.804,-62.823 h1.52
  text ".Print_Time" at 51.321,-62.823 h1.52
  text "TEXAS INSTRUMENTS" at 83.439,-62.823 h1.52
M12 Stackup:
  drawing of 191 lines, arcs and shapes, not listed
  text "Layer" at 203.037,164.235 h1.52
  text "Name" at 213.449,164.235 h1.52
  text "Material" at 237.065,164.235 h1.52
  text "Thickness" at 258.903,164.235 h1.52
  text "Constant" at 275.408,164.235 h1.52
  text "Board Layer Stack" at 289.883,164.235 h1.52
  text "Top Overlay" at 213.449,161.187 h1.52
  text "Top Solder" at 213.449,158.139 h1.52
  text "Solder Resist" at 237.065,158.139 h1.52
  text "0.40mil" at 258.903,158.139 h1.52
  text "3.5" at 275.408,158.139 h1.52
  text "1" at 203.037,155.091 h1.52
  text "Top Layer" at 213.449,155.091 h1.52
  text "2.80mil" at 258.903,155.091 h1.52
  text "Dielectric1" at 213.449,152.043 h1.52
  text "FR-4 High Tg" at 237.065,152.043 h1.52
  text "59.20mil" at 258.903,152.043 h1.52
  text "4.8" at 275.408,152.043 h1.52
  text "2" at 203.037,148.995 h1.52
  text "Bottom Layer" at 213.449,148.995 h1.52
  text "2.80mil" at 258.903,148.995 h1.52
  text "Bottom Solder" at 213.449,145.947 h1.52
  text "Solder Resist" at 237.065,145.947 h1.52
  text "0.40mil" at 258.903,145.947 h1.52
  text "3.5" at 275.408,145.947 h1.52
  text "Bottom Overlay" at 213.449,142.899 h1.52
  text ".Layer_Name" at -31.775,-57.594 h1.52
M13 Component Bodies Top:
  text ".Layer_Name" at -31.775,-57.594 h1.52
M14 Component Bodies Bottom:
  text ".Layer_Name" at -31.775,-57.594 h1.52
M15 Courtyards Top:
  text ".Layer_Name" at -31.775,-57.594 h1.52
M16 Courtyards Bottom:
  text ".Layer_Name" at -31.775,-57.594 h1.52
Drill Drawing:
  circle w0.254: c89.807,47.785 r0.702
  lines w0.254: 89.105,43.925 90.509,43.925 90.509,45.329 89.105,45.329 89.105,43.925
  lines w0.305: 87.833,42.978 169.913,42.978 ; 87.833,49.293 169.913,49.293 ; 96.415,39.82 96.415,52.451 ; 104.848,39.82 104.848,52.451 ; 121.016,39.82 121.016,52.451 ; 127.599,39.82 127.599,52.451 ; 137.128,39.82 137.128,52.451 ; 155.526,39.82 155.526,52.451 ; 87.833,39.82 169.913,39.82 169.913,52.451 87.833,52.451 87.833,39.82
  text "Symbol" at 89.728,50.241 h1.83
  text "Quantity" at 97.362,50.241 h1.83
  text "Finished Hole Size" at 105.795,50.241 h1.83
  text "Plated" at 121.964,50.241 h1.83
  text "Hole Type" at 128.546,50.241 h1.83
  text "Drill Layer Pair" at 138.075,50.241 h1.83
  text "Hole Tolerance" at 156.473,50.241 h1.83
  text "50" at 97.362,47.083 h1.52
  text "12.00mil (0.305mm)" at 105.795,47.083 h1.52
  text "PTH" at 121.964,47.083 h1.52
  text "Round" at 128.546,47.083 h1.52
  text "Top Layer - Bottom Layer" at 138.075,47.083 h1.52
  text "2" at 97.362,43.925 h1.52
  text "78.74mil (2.000mm)" at 105.795,43.925 h1.52
  text "PTH" at 121.964,43.925 h1.52
  text "Round" at 128.546,43.925 h1.52
  text "Top Layer - Bottom Layer" at 138.075,43.925 h1.52
  text "52 Total" at 97.362,40.767 h1.52
  text ".Layer_Name" at -31.775,-57.594 h1.52
M17 Embedded Cavity:
  text ".Layer_Name" at -31.775,-57.594 h1.52
M18 Embedded Assembly:
  text ".Layer_Name" at -31.775,-57.594 h1.52
M19 Embedded Keepout:
  text ".Layer_Name" at -31.775,-57.594 h1.52

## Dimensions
-15.011,-0.254 to 15.011,0 on M2 Board Dimensions
-6.25,-18.8 to -0.254,15.011 on M2 Board Dimensions
-46.431,-45.949 to -21.031,-45.949 on M2 Board Dimensions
